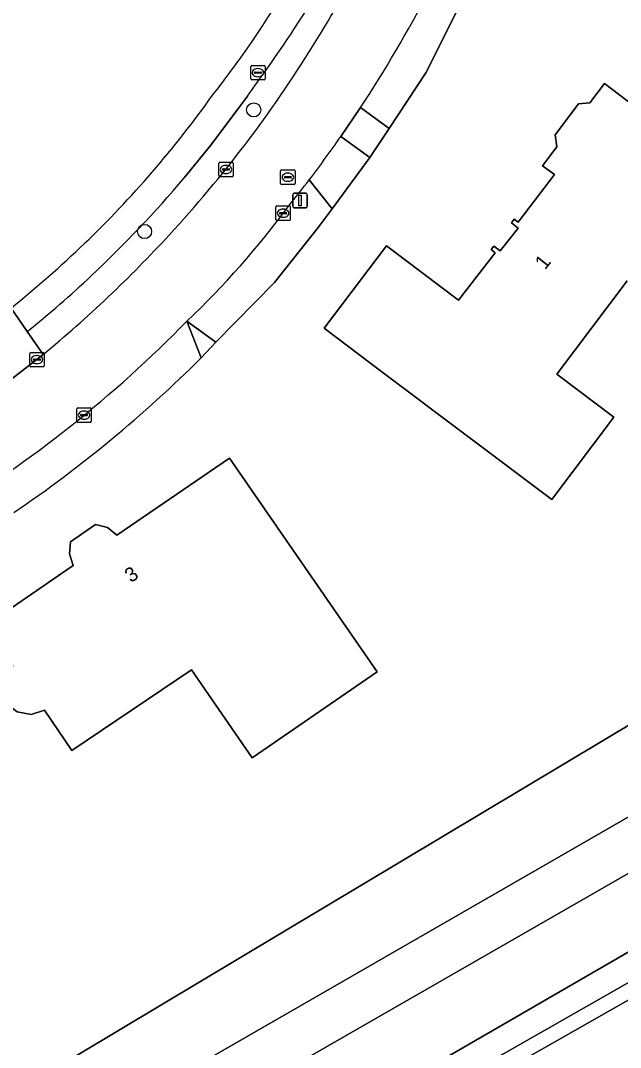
# Model space of a CAD drawing. Extents: x 162417 to 163722, y 384268 to 385417.
# Drawn here: x 163420 to 163461.6, y 384584.8 to 384656 of the extents above; entities that cross this region are included whole.
import ezdxf

# ---------------------------------------------------------------- set-up
doc = ezdxf.new("R2010")
doc.units = 0
for name, color, linetype in [('IMGEO_Berm_groen', 7, 'Continuous'), ('IMGEO_Boom', 7, 'Continuous'), ('IMGEO_Brandkraan', 7, 'Continuous'), ('IMGEO_Erf', 7, 'Continuous'), ('IMGEO_Fietspad_gesloten', 7, 'Continuous'), ('IMGEO_Groenvoorziening', 7, 'Continuous'), ('IMGEO_Hek', 7, 'Continuous'), ('IMGEO_Kolk', 7, 'Continuous'), ('IMGEO_Lichtmast', 7, 'Continuous'), ('IMGEO_Pand', 7, 'Continuous'), ('IMGEO_Pand_nummerreeks', 7, 'Continuous'), ('IMGEO_Rijbaan_lokaal_open', 7, 'Continuous'), ('IMGEO_Rioolput', 7, 'Continuous'), ('IMGEO_Voetpad_open', 7, 'Continuous')]:
    doc.layers.add(name, color=color, linetype=linetype)

msp = doc.modelspace()

# ---------------------------------------------------------------- linework, layer by layer
at = {"layer": 'IMGEO_Berm_groen'}
for points in [[(163435.757, 384650.725), (163433.233, 384647.339), (163431.375, 384645.06)], [(163420.504, 384634.421), (163421.605, 384632.827)]]:
    msp.add_lwpolyline(points, dxfattribs=at)
for centre, radius, start, end in [((163372.322, 384697.23), 80.439, 327.69017, 333.08477), ((163349.96, 384713.846), 106.515, 323.65813, 327.78495), ((163367.687, 384699.024), 85.321, 317.24489, 328.33568), ((163369, 384697.794), 81.679, 313.23065, 319.78787), ((163366.109, 384700.117), 87.222, 309.51339, 317.42123), ((163375.608, 384690.545), 71.872, 308.65738, 313.34994)]:
    msp.add_arc(centre, radius, start, end, dxfattribs=at)
at = {"layer": 'IMGEO_Boom'}
for centre in [(163436.189, 384649.77), (163428.634, 384641.348)]:
    msp.add_circle(centre, 0.489, dxfattribs=at)
at = {"layer": 'IMGEO_Brandkraan'}
for p, q in [((163435.983, 384651.925), (163435.983, 384652.777)), ((163436.058, 384652.851), (163436.91, 384652.851)), ((163436.471, 384652.631), (163436.496, 384652.631)), ((163436.984, 384652.777), (163436.984, 384651.925)), ((163436.242, 384652.345), (163436.242, 384652.357)), ((163436.68, 384652.308), (163436.282, 384652.308)), ((163436.285, 384652.394), (163436.683, 384652.394)), ((163436.494, 384652.071), (163436.469, 384652.071)), ((163436.726, 384652.357), (163436.726, 384652.345)), ((163436.91, 384651.851), (163436.058, 384651.851))]:
    msp.add_line(p, q, dxfattribs=at)
for points in [[(163435.983, 384651.925), (163435.983, 384652.777)], [(163436.058, 384652.851), (163436.91, 384652.851)], [(163436.984, 384652.777), (163436.984, 384651.925)], [(163436.91, 384651.851), (163436.058, 384651.851)]]:
    msp.add_lwpolyline(points, dxfattribs=at)
for centre, radius, start, end in [((163436.06, 384652.775), 0.0765, 91.55205, 178.44795), ((163436.06, 384652.775), 0.0765, 91.55205, 178.44795), ((163436.908, 384652.775), 0.0765, 1.55205, 88.44795), ((163436.908, 384652.775), 0.0765, 1.55205, 88.44795), ((163436.06, 384651.927), 0.0765, 181.55205, 268.44795), ((163436.06, 384651.927), 0.0765, 181.55205, 268.44795), ((163436.282, 384652.354), 0.0403, 85.87752, 175.75265), ((163436.279, 384652.344), 0.0366, 178.93798, 274.71019), ((163436.683, 384652.351), 0.043, 264.86636, 352.45326), ((163436.687, 384652.356), 0.0386, 1.73085, 96.63898), ((163436.908, 384651.927), 0.0765, 271.55205, 358.44795), ((163436.908, 384651.927), 0.0765, 271.55205, 358.44795)]:
    msp.add_arc(centre, radius, start, end, dxfattribs=at)
for centre, major_axis, ratio, start_param, end_param in [((163436.47, 384652.351), (-0.387, 0.002), 0.722429, 4.712389, 7.853982), ((163436.495, 384652.351), (-0.39, 0.002), 0.717154, 1.570796, 4.712389)]:
    msp.add_ellipse(centre, major_axis=major_axis, ratio=ratio, start_param=start_param, end_param=end_param, dxfattribs=at)
at = {"layer": 'IMGEO_Erf'}
for points in [[(163477.053, 384616.061), (163494.178, 384625.448), (163492.655, 384633.034), (163488.848, 384640.395), (163490.386, 384642.261), (163485.646, 384644.406), (163474.172, 384657.022), (163458.908, 384673.806), (163458.848, 384673.73), (163448.112, 384652.334), (163445.562, 384648.482), (163444.229, 384646.468), (163441.62, 384642.927), (163440.661, 384641.624), (163437.621, 384637.821), (163433.577, 384633.672), (163432.556, 384632.606)], [(163462.05, 384637.926), (163457.183, 384631.465), (163461.128, 384628.492), (163456.834, 384622.787), (163445.072, 384631.638), (163441.077, 384634.645), (163445.376, 384640.357), (163450.384, 384636.587), (163452.913, 384639.878), (163452.64, 384640.096), (163452.824, 384640.343), (163453.271, 384640.002), (163454.503, 384641.582), (163454.052, 384641.949), (163454.23, 384642.204), (163454.511, 384641.994), (163457.021, 384645.287), (163456.192, 384645.905), (163457.188, 384647.216), (163457.07, 384648.042), (163458.687, 384650.185), (163459.478, 384650.272), (163460.492, 384651.6), (163464.466, 384648.566)], [(163339.91, 384591.461), (163333.246, 384589.206), (163336.72, 384578.855), (163337.075, 384577.799), (163340.673, 384567.341), (163339.733, 384567.052), (163345.242, 384548.875), (163353.612, 384549.684), (163356.302, 384545.212), (163410.245, 384576.085), (163477.053, 384616.061)]]:
    msp.add_lwpolyline(points, dxfattribs=at)
msp.add_lwpolyline([(163423.426, 384619.015), (163423.504, 384619.857), (163425.24, 384621.047), (163426.06, 384620.847), (163426.722, 384620.31), (163434.524, 384625.652), (163437.361, 384621.535), (163444.73, 384610.844), (163436.077, 384604.88), (163431.875, 384610.985), (163423.588, 384605.386), (163421.696, 384608.187), (163420.775, 384607.881), (163419.813, 384608.066), (163419.044, 384608.641), (163418.702, 384609.538), (163418.883, 384610.501), (163419.499, 384611.264), (163417.6, 384614.035), (163423.689, 384618.208)], close=True, dxfattribs=at)
for centre, radius, start, end in [((163383.007, 384690.738), 64.258, 321.562, 330.99773), ((163374.28, 384692.806), 72.479, 313.8396, 324.57181), ((163373.98, 384692.802), 72.684, 308.65684, 314.01186), ((163368.694, 384696.602), 90.409, 304.2543, 314.94032)]:
    msp.add_arc(centre, radius, start, end, dxfattribs=at)
at = {"layer": 'IMGEO_Fietspad_gesloten'}
msp.add_lwpolyline([(163557.356, 384642.39), (163544.377, 384634.733), (163522.824, 384622.528), (163511.147, 384615.916), (163500, 384609.604), (163484.5, 384600.835), (163415.868, 384561.799), (163356.283, 384527.511), (163355.13, 384526.85), (163345.851, 384521.528), (163335.19, 384515.322), (163308.868, 384500), (163214.308, 384444.956), (163137.001, 384399.432), (163115.639, 384387.124)], dxfattribs=at)
at = {"layer": 'IMGEO_Groenvoorziening'}
for points in [[(163443.594, 384649.939), (163445.562, 384648.482), (163448.112, 384652.334), (163458.848, 384673.73), (163457.666, 384674.338), (163460.408, 384679.673), (163459.405, 384680.232), (163448.271, 384657.924)], [(163444.229, 384646.468), (163442.225, 384647.922)], [(163440.042, 384644.937), (163441.62, 384642.927), (163444.229, 384646.468)], [(163499.848, 384626.963), (163497.993, 384631.968), (163492.657, 384639.09), (163494.067, 384640.596), (163490.386, 384642.261), (163488.848, 384640.395), (163492.655, 384633.034), (163494.178, 384625.448), (163477.053, 384616.061), (163410.245, 384576.085), (163356.302, 384545.212), (163353.612, 384549.684), (163345.242, 384548.875), (163350.849, 384530.373)], [(163354.498, 384529.757), (163418.315, 384566.067), (163500, 384613.359), (163507.381, 384617.632), (163508.242, 384618.879), (163503.384, 384623.682)], [(163501.9, 384620.876), (163500, 384619.404), (163496.132, 384616.406), (163415.728, 384570.225), (163353.961, 384535.291), (163350.391, 384546.23), (163352.187, 384546.648), (163356.605, 384540.896), (163412.421, 384572.167), (163489.45, 384616.524), (163497.843, 384621.571)], [(163497.843, 384621.571), (163489.45, 384616.524), (163412.421, 384572.167), (163356.605, 384540.896), (163352.187, 384546.648), (163350.391, 384546.23), (163353.961, 384535.291), (163415.728, 384570.225), (163496.132, 384616.406), (163500, 384619.404), (163501.9, 384620.876)], [(163350.849, 384530.373), (163351.378, 384528.626), (163354.09, 384527.692), (163510.332, 384616.812), (163508.242, 384618.879), (163507.381, 384617.632), (163500, 384613.359), (163418.315, 384566.067), (163354.498, 384529.757)], [(163484.5, 384600.835), (163500, 384609.604), (163511.147, 384615.916), (163510.332, 384616.812), (163354.09, 384527.692), (163351.378, 384528.626), (163350.849, 384530.373), (163349.875, 384531.237), (163348.952, 384532.055), (163349.144, 384531.395), (163350.417, 384529.001), (163351.106, 384528.064), (163351.626, 384527.495)], [(163355.13, 384526.85), (163356.283, 384527.511), (163415.868, 384561.799), (163484.5, 384600.835)]]:
    msp.add_lwpolyline(points, dxfattribs=at)
msp.add_lwpolyline([(163433.577, 384633.672), (163431.562, 384635.143), (163432.556, 384632.606)], close=True, dxfattribs=at)
for centre, radius, start, end in [((163370.348, 384698.203), 87.718, 326.61785, 332.66515), ((163368.427, 384699.601), 90.094, 322.64513, 324.99712)]:
    msp.add_arc(centre, radius, start, end, dxfattribs=at)
at = {"layer": 'IMGEO_Hek'}
msp.add_lwpolyline([(163510.332, 384616.812), (163354.09, 384527.692), (163351.378, 384528.626), (163350.849, 384530.373)], dxfattribs=at)
at = {"layer": 'IMGEO_Kolk'}
for p, q in [((163433.772, 384645.219), (163433.772, 384646.071)), ((163433.847, 384646.145), (163434.699, 384646.145)), ((163434.031, 384645.639), (163434.031, 384645.651)), ((163434.469, 384645.602), (163434.071, 384645.602)), ((163434.074, 384645.688), (163434.472, 384645.688)), ((163434.26, 384645.925), (163434.285, 384645.925)), ((163434.515, 384645.651), (163434.515, 384645.639)), ((163434.773, 384646.071), (163434.773, 384645.219)), ((163434.699, 384645.145), (163433.847, 384645.145)), ((163434.283, 384645.365), (163434.258, 384645.365)), ((163437.726, 384642.189), (163437.726, 384643.041)), ((163437.801, 384643.115), (163438.653, 384643.115)), ((163437.985, 384642.609), (163437.985, 384642.621)), ((163438.028, 384642.658), (163438.426, 384642.658)), ((163438.214, 384642.895), (163438.239, 384642.895)), ((163438.469, 384642.621), (163438.469, 384642.609)), ((163438.727, 384643.041), (163438.727, 384642.189)), ((163438.653, 384642.115), (163437.801, 384642.115)), ((163438.423, 384642.572), (163438.025, 384642.572)), ((163438.237, 384642.335), (163438.212, 384642.335)), ((163420.679, 384632.046), (163420.679, 384632.898)), ((163420.754, 384632.972), (163421.606, 384632.972)), ((163421.167, 384632.752), (163421.192, 384632.752)), ((163421.68, 384632.898), (163421.68, 384632.046)), ((163421.606, 384631.972), (163420.754, 384631.972)), ((163420.938, 384632.466), (163420.938, 384632.478)), ((163421.376, 384632.429), (163420.978, 384632.429)), ((163420.981, 384632.515), (163421.379, 384632.515)), ((163421.19, 384632.192), (163421.165, 384632.192)), ((163421.422, 384632.478), (163421.422, 384632.466)), ((163424.016, 384629.128), (163424.868, 384629.128)), ((163423.941, 384628.202), (163423.941, 384629.054)), ((163424.2, 384628.622), (163424.2, 384628.634)), ((163424.638, 384628.585), (163424.24, 384628.585)), ((163424.243, 384628.671), (163424.641, 384628.671)), ((163424.429, 384628.908), (163424.454, 384628.908)), ((163424.684, 384628.634), (163424.684, 384628.622)), ((163424.942, 384629.054), (163424.942, 384628.202)), ((163424.868, 384628.128), (163424.016, 384628.128)), ((163424.452, 384628.348), (163424.427, 384628.348))]:
    msp.add_line(p, q, dxfattribs=at)
for points in [[(163433.772, 384645.219), (163433.772, 384646.071)], [(163433.847, 384646.145), (163434.699, 384646.145)], [(163434.773, 384646.071), (163434.773, 384645.219)], [(163434.699, 384645.145), (163433.847, 384645.145)], [(163437.726, 384642.189), (163437.726, 384643.041)], [(163437.801, 384643.115), (163438.653, 384643.115)], [(163438.727, 384643.041), (163438.727, 384642.189)], [(163438.653, 384642.115), (163437.801, 384642.115)], [(163420.679, 384632.046), (163420.679, 384632.898)], [(163420.754, 384632.972), (163421.606, 384632.972)], [(163421.68, 384632.898), (163421.68, 384632.046)], [(163421.606, 384631.972), (163420.754, 384631.972)], [(163424.016, 384629.128), (163424.868, 384629.128)], [(163423.941, 384628.202), (163423.941, 384629.054)], [(163424.942, 384629.054), (163424.942, 384628.202)], [(163424.868, 384628.128), (163424.016, 384628.128)]]:
    msp.add_lwpolyline(points, dxfattribs=at)
for centre, radius, start, end in [((163433.849, 384646.069), 0.0765, 91.55205, 178.44795), ((163433.849, 384646.069), 0.0765, 91.55205, 178.44795), ((163434.071, 384645.648), 0.0403, 85.87752, 175.75265), ((163434.068, 384645.638), 0.0366, 178.93798, 274.71019), ((163434.472, 384645.645), 0.043, 264.86636, 352.45326), ((163434.476, 384645.65), 0.0386, 1.73085, 96.63898), ((163434.697, 384646.069), 0.0765, 1.55205, 88.44795), ((163434.697, 384646.069), 0.0765, 1.55205, 88.44795), ((163433.849, 384645.221), 0.0765, 181.55205, 268.44795), ((163433.849, 384645.221), 0.0765, 181.55205, 268.44795), ((163434.697, 384645.221), 0.0765, 271.55205, 358.44795), ((163434.697, 384645.221), 0.0765, 271.55205, 358.44795), ((163437.803, 384643.039), 0.0765, 91.55205, 178.44795), ((163437.803, 384643.039), 0.0765, 91.55205, 178.44795), ((163438.025, 384642.618), 0.0403, 85.87752, 175.75265), ((163438.43, 384642.62), 0.0386, 1.73085, 96.63898), ((163438.651, 384643.039), 0.0765, 1.55205, 88.44795), ((163438.651, 384643.039), 0.0765, 1.55205, 88.44795), ((163437.803, 384642.191), 0.0765, 181.55205, 268.44795), ((163437.803, 384642.191), 0.0765, 181.55205, 268.44795), ((163438.022, 384642.608), 0.0366, 178.93798, 274.71019), ((163438.426, 384642.615), 0.043, 264.86636, 352.45326), ((163438.651, 384642.191), 0.0765, 271.55205, 358.44795), ((163438.651, 384642.191), 0.0765, 271.55205, 358.44795), ((163420.756, 384632.896), 0.0765, 91.55205, 178.44795), ((163420.756, 384632.896), 0.0765, 91.55205, 178.44795), ((163421.604, 384632.896), 0.0765, 1.55205, 88.44795), ((163421.604, 384632.896), 0.0765, 1.55205, 88.44795), ((163420.756, 384632.048), 0.0765, 181.55205, 268.44795), ((163420.756, 384632.048), 0.0765, 181.55205, 268.44795), ((163420.978, 384632.475), 0.0403, 85.87752, 175.75265), ((163420.975, 384632.465), 0.0366, 178.93798, 274.71019), ((163421.379, 384632.472), 0.043, 264.86636, 352.45326), ((163421.383, 384632.477), 0.0386, 1.73085, 96.63898), ((163421.604, 384632.048), 0.0765, 271.55205, 358.44795), ((163421.604, 384632.048), 0.0765, 271.55205, 358.44795), ((163424.018, 384629.052), 0.0765, 91.55205, 178.44795), ((163424.018, 384629.052), 0.0765, 91.55205, 178.44795), ((163424.866, 384629.052), 0.0765, 1.55205, 88.44795), ((163424.866, 384629.052), 0.0765, 1.55205, 88.44795), ((163424.24, 384628.631), 0.0403, 85.87752, 175.75265), ((163424.237, 384628.621), 0.0366, 178.93798, 274.71019), ((163424.641, 384628.628), 0.043, 264.86636, 352.45326), ((163424.645, 384628.633), 0.0386, 1.73085, 96.63898), ((163424.018, 384628.204), 0.0765, 181.55205, 268.44795), ((163424.018, 384628.204), 0.0765, 181.55205, 268.44795), ((163424.866, 384628.204), 0.0765, 271.55205, 358.44795), ((163424.866, 384628.204), 0.0765, 271.55205, 358.44795)]:
    msp.add_arc(centre, radius, start, end, dxfattribs=at)
for centre, major_axis, ratio, start_param, end_param in [((163434.259, 384645.645), (-0.387, 0.002), 0.722429, 4.712389, 7.853982), ((163434.284, 384645.645), (-0.39, 0.002), 0.717154, 1.570796, 4.712389), ((163438.213, 384642.615), (-0.387, 0.002), 0.722429, 4.712389, 7.853982), ((163438.238, 384642.615), (-0.39, 0.002), 0.717154, 1.570796, 4.712389), ((163421.166, 384632.472), (-0.387, 0.002), 0.722429, 4.712389, 7.853982), ((163421.191, 384632.472), (-0.39, 0.002), 0.717154, 1.570796, 4.712389), ((163424.428, 384628.628), (-0.387, 0.002), 0.722429, 4.712389, 7.853982), ((163424.453, 384628.628), (-0.39, 0.002), 0.717154, 1.570796, 4.712389)]:
    msp.add_ellipse(centre, major_axis=major_axis, ratio=ratio, start_param=start_param, end_param=end_param, dxfattribs=at)
at = {"layer": 'IMGEO_Lichtmast'}
for p, q in [((163438.904, 384643.098), (163438.904, 384643.898)), ((163438.904, 384643.898), (163438.904, 384643.098)), ((163439.004, 384643.998), (163439.794, 384643.998)), ((163439.794, 384643.998), (163439.004, 384643.998)), ((163439.894, 384643.898), (163439.894, 384643.098)), ((163439.894, 384643.098), (163439.894, 384643.898)), ((163439.794, 384642.998), (163439.004, 384642.998)), ((163439.004, 384642.998), (163439.794, 384642.998))]:
    msp.add_line(p, q, dxfattribs=at)
msp.add_lwpolyline([(163439.324, 384643.873), (163439.474, 384643.873), (163439.474, 384643.123), (163439.324, 384643.123), (163439.324, 384643.873)], dxfattribs=at)
for centre, start, end in [((163439.004, 384643.898), 90, 180), ((163439.004, 384643.898), 90, 180), ((163439.794, 384643.898), 0, 90), ((163439.794, 384643.898), 360, 90), ((163439.004, 384643.098), 180, 270), ((163439.004, 384643.098), 180, 270), ((163439.794, 384643.098), 270, 0), ((163439.794, 384643.098), 270, 0)]:
    msp.add_arc(centre, 0.1, start, end, dxfattribs=at)
at = {"layer": 'IMGEO_Pand'}
msp.add_lwpolyline([(163464.466, 384648.566), (163460.492, 384651.6), (163459.478, 384650.272), (163458.687, 384650.185), (163457.07, 384648.042), (163457.188, 384647.216), (163456.192, 384645.905), (163457.021, 384645.287), (163454.511, 384641.994), (163454.23, 384642.204), (163454.052, 384641.949), (163454.503, 384641.582), (163453.271, 384640.002), (163452.824, 384640.343), (163452.64, 384640.096), (163452.913, 384639.878), (163450.384, 384636.587), (163445.376, 384640.357), (163441.077, 384634.645), (163445.072, 384631.638), (163456.834, 384622.787), (163461.128, 384628.492), (163457.183, 384631.465), (163462.05, 384637.926)], dxfattribs=at)
msp.add_lwpolyline([(163419.499, 384611.264), (163418.883, 384610.501), (163418.702, 384609.538), (163419.044, 384608.641), (163419.813, 384608.066), (163420.775, 384607.881), (163421.696, 384608.187), (163423.588, 384605.386), (163431.875, 384610.985), (163436.077, 384604.88), (163444.73, 384610.844), (163437.361, 384621.535), (163434.524, 384625.652), (163426.722, 384620.31), (163426.06, 384620.847), (163425.24, 384621.047), (163423.504, 384619.857), (163423.426, 384619.015), (163423.689, 384618.208), (163417.6, 384614.035)], close=True, dxfattribs=at)
at = {"layer": 'IMGEO_Rijbaan_lokaal_open'}
for points in [[(163442.225, 384647.922), (163443.594, 384649.939)], [(163421.605, 384632.827), (163417.131, 384629.372), (163416.038, 384628.57), (163412.543, 384626.296), (163408.832, 384624.02), (163408.641, 384623.903), (163406.014, 384622.456), (163405.506, 384622.218), (163399.158, 384619.244), (163396.153, 384618.151), (163391.36, 384616.408), (163390.546, 384616.112), (163376.658, 384611.416)]]:
    msp.add_lwpolyline(points, dxfattribs=at)
for centre, radius, start, end in [((163372.322, 384697.23), 80.439, 327.69017, 333.08477), ((163370.348, 384698.203), 87.718, 326.61785, 332.66515), ((163367.687, 384699.024), 85.321, 317.24489, 328.33568), ((163368.427, 384699.601), 90.094, 322.64513, 324.99712), ((163371.918, 384696.918), 85.691, 321.10831, 322.65514), ((163390.205, 384678.824), 60.154, 313.43502, 323.58755), ((163366.109, 384700.117), 87.222, 309.51339, 317.42123), ((163370.506, 384694.597), 85.221, 301.14686, 315.76166)]:
    msp.add_arc(centre, radius, start, end, dxfattribs=at)
at = {"layer": 'IMGEO_Rioolput'}
for p, q in [((163438.057, 384644.682), (163438.057, 384645.534)), ((163438.132, 384645.608), (163438.984, 384645.608)), ((163439.058, 384645.534), (163439.058, 384644.682)), ((163438.316, 384645.102), (163438.316, 384645.114)), ((163438.754, 384645.065), (163438.356, 384645.065)), ((163438.359, 384645.151), (163438.757, 384645.151)), ((163438.568, 384644.828), (163438.543, 384644.828)), ((163438.545, 384645.388), (163438.57, 384645.388)), ((163438.8, 384645.114), (163438.8, 384645.102)), ((163438.984, 384644.608), (163438.132, 384644.608))]:
    msp.add_line(p, q, dxfattribs=at)
for points in [[(163438.057, 384644.682), (163438.057, 384645.534)], [(163438.132, 384645.608), (163438.984, 384645.608)], [(163439.058, 384645.534), (163439.058, 384644.682)], [(163438.984, 384644.608), (163438.132, 384644.608)]]:
    msp.add_lwpolyline(points, dxfattribs=at)
for centre, radius, start, end in [((163438.134, 384645.532), 0.0765, 91.55205, 178.44795), ((163438.134, 384645.532), 0.0765, 91.55205, 178.44795), ((163438.982, 384645.532), 0.0765, 1.55205, 88.44795), ((163438.982, 384645.532), 0.0765, 1.55205, 88.44795), ((163438.356, 384645.111), 0.0403, 85.87752, 175.75265), ((163438.353, 384645.101), 0.0366, 178.93798, 274.71019), ((163438.757, 384645.108), 0.043, 264.86636, 352.45326), ((163438.761, 384645.113), 0.0386, 1.73085, 96.63898), ((163438.134, 384644.684), 0.0765, 181.55205, 268.44795), ((163438.134, 384644.684), 0.0765, 181.55205, 268.44795), ((163438.982, 384644.684), 0.0765, 271.55205, 358.44795), ((163438.982, 384644.684), 0.0765, 271.55205, 358.44795)]:
    msp.add_arc(centre, radius, start, end, dxfattribs=at)
for centre, major_axis, ratio, start_param, end_param in [((163438.544, 384645.108), (-0.387, 0.002), 0.722429, 4.712389, 7.853982), ((163438.569, 384645.108), (-0.39, 0.002), 0.717154, 1.570796, 4.712389)]:
    msp.add_ellipse(centre, major_axis=major_axis, ratio=ratio, start_param=start_param, end_param=end_param, dxfattribs=at)
at = {"layer": 'IMGEO_Voetpad_open'}
for points in [[(163431.375, 384645.06), (163433.233, 384647.339), (163435.757, 384650.725)], [(163440.661, 384641.624), (163441.62, 384642.927), (163440.042, 384644.937)], [(163431.562, 384635.143), (163433.577, 384633.672), (163437.621, 384637.821), (163440.661, 384641.624)], [(163413.713, 384631.935), (163414.832, 384630.315), (163416.038, 384628.57), (163417.131, 384629.372), (163421.605, 384632.827), (163420.504, 384634.421), (163419.383, 384636.043)], [(163419.383, 384636.043), (163420.504, 384634.421)], [(163432.556, 384632.606), (163431.562, 384635.143)]]:
    msp.add_lwpolyline(points, dxfattribs=at)
msp.add_lwpolyline([(163442.225, 384647.922), (163444.229, 384646.468), (163445.562, 384648.482), (163443.594, 384649.939)], close=True, dxfattribs=at)
for centre, radius, start, end in [((163383.007, 384690.738), 64.258, 321.562, 330.99773), ((163349.96, 384713.846), 106.515, 323.65813, 327.78495), ((163374.28, 384692.806), 72.479, 313.8396, 324.57181), ((163369, 384697.794), 81.679, 313.23065, 319.78787), ((163371.918, 384696.918), 85.691, 321.10831, 322.65514), ((163390.205, 384678.824), 60.154, 313.43502, 323.58755), ((163373.98, 384692.802), 72.684, 308.65684, 314.01186), ((163375.608, 384690.545), 71.872, 308.65738, 313.34994), ((163370.506, 384694.597), 85.221, 301.14686, 315.76166), ((163368.694, 384696.602), 90.409, 304.2543, 314.94032)]:
    msp.add_arc(centre, radius, start, end, dxfattribs=at)

# ---------------------------------------------------------------- texts
at = {"layer": 'IMGEO_Pand_nummerreeks'}
for s, rotation, p in [('1', 52.05479, (163456.374, 384638.648)), ('3', 34.46655, (163427.691, 384616.984))]:
    msp.add_text(s, height=1, rotation=rotation, dxfattribs=at).set_placement(p)

doc.saveas('drawing.dxf')
